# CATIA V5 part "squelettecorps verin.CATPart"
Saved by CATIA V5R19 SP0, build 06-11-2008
Part number: squelette corps verin
Bounding box of the stored display mesh (mm): x 0 to 0, y 11 to 26, z 6 to 31
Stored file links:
  C:\Users\Gauthier\Documents\IFMA\IAO\TP2\squelettecorps verin.CATPart
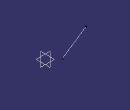
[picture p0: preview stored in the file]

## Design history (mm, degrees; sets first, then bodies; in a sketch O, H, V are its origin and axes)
Line1: stored without definition
Line2: type PtPt, SecondPoint Point2, FirstPoint Point1
Set1
  Point1: stored without definition
  Point2: stored without definition
Body1 (main body)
